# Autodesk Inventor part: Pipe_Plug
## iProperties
Author: John Muchow
Shininess: 86.0
PropertySet Name: _Private Model Information
Created: 2001-04
Part Number: Pipe_Plug
Document SubType Name: Modeling
Designer: John Muchow
Material: Brass, Soft Yellow
Control State: 0
Master: False
Checked Out: False
PropertySet Name: Design Tracking Control
Density: 8.03
Volumn: 3.7971378569260024
Area: 13.95780369460519
PropertySet Name: Model Information
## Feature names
1. Extrusion1
2. Revolution1
3. Chamfer1
4. Chamfer2
